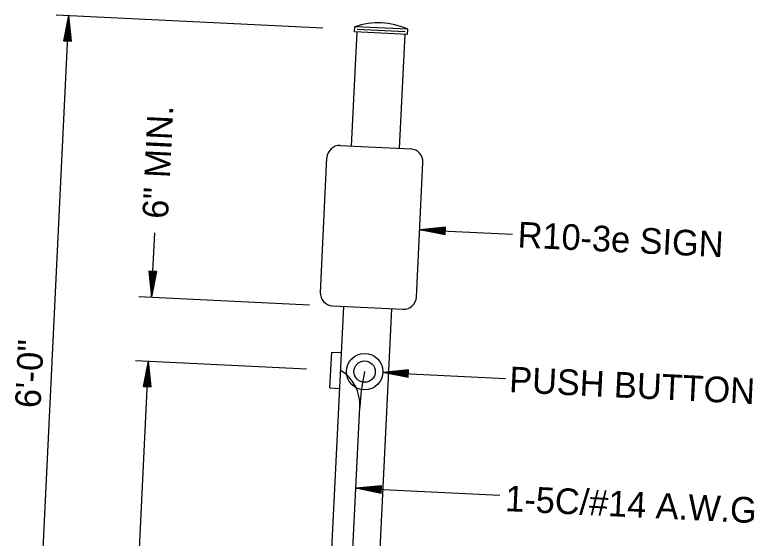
# Model space of a CAD drawing. Extents: x 661018 to 663325, y 642537 to 643074.
# Drawn here: x 661690.1 to 661787.2, y 642866.3 to 642935 of the extents above; entities that cross this region are included whole.
import ezdxf

# ---------------------------------------------------------------- set-up
doc = ezdxf.new("R2010")
doc.units = 0
doc.layers.add('R_Dimension', color=7, linetype='Continuous')

msp = doc.modelspace()

# ---------------------------------------------------------------- linework, layer by layer
at = {"layer": 'R_Dimension'}
for p, q in [((661692.169, 642831.3), (661697.202, 642934.948)), ((661695.52, 642935.03), (661730.561, 642933.328)), ((661696.534, 642931.607), (661697.202, 642934.948)), ((661697.544, 642931.558), (661697.202, 642934.948)), ((661696.618, 642931.603), (661697.175, 642934.386)), ((661697.46, 642931.562), (661697.175, 642934.386)), ((661696.704, 642931.599), (661697.147, 642933.807)), ((661696.788, 642931.595), (661697.12, 642933.247)), ((661697.29, 642931.571), (661697.12, 642933.247)), ((661697.374, 642931.567), (661697.147, 642933.807)), ((661734.709, 642932.79), (661734.741, 642933.463)), ((661741.724, 642933.123), (661734.741, 642933.463)), ((661741.372, 642932.803), (661735.062, 642933.11)), ((661741.692, 642932.45), (661741.724, 642933.123)), ((661696.876, 642931.591), (661697.092, 642932.677)), ((661696.96, 642931.587), (661697.065, 642932.115)), ((661697.118, 642931.579), (661697.065, 642932.115)), ((661697.204, 642931.575), (661697.092, 642932.677)), ((661734.318, 642917.8), (661735.045, 642932.773)), ((661741.692, 642932.45), (661734.709, 642932.79)), ((661740.628, 642917.494), (661741.355, 642932.467)), ((661696.534, 642931.607), (661697.544, 642931.558)), ((661732.846, 642917.872), (661742.1, 642917.423)), ((661730.224, 642898.603), (661731.082, 642916.271)), ((661742.843, 642897.991), (661743.701, 642915.658)), ((661746.662, 642907.166), (661743.272, 642906.824)), ((661743.272, 642906.824), (661755.458, 642906.233)), ((661746.613, 642906.156), (661743.272, 642906.824)), ((661746.658, 642907.082), (661743.834, 642906.797)), ((661746.617, 642906.24), (661743.834, 642906.797)), ((661746.654, 642906.996), (661744.413, 642906.769)), ((661746.621, 642906.326), (661744.413, 642906.769)), ((661746.65, 642906.912), (661744.974, 642906.742)), ((661746.646, 642906.826), (661745.544, 642906.714)), ((661746.613, 642906.156), (661746.662, 642907.166)), ((661708.057, 642897.993), (661708.466, 642906.406)), ((661746.626, 642906.41), (661744.974, 642906.742)), ((661746.63, 642906.498), (661745.544, 642906.714)), ((661746.642, 642906.74), (661746.106, 642906.687)), ((661746.634, 642906.582), (661746.106, 642906.687)), ((661707.716, 642901.383), (661708.057, 642897.993)), ((661708.726, 642901.334), (661707.716, 642901.383)), ((661707.8, 642901.379), (661708.085, 642898.555)), ((661707.886, 642901.375), (661708.113, 642899.134)), ((661707.97, 642901.371), (661708.14, 642899.694)), ((661708.056, 642901.366), (661708.168, 642900.265)), ((661708.726, 642901.334), (661708.057, 642897.993)), ((661708.641, 642901.338), (661708.085, 642898.555)), ((661708.556, 642901.342), (661708.113, 642899.134)), ((661708.471, 642901.346), (661708.14, 642899.694)), ((661708.142, 642901.362), (661708.195, 642900.827)), ((661708.384, 642901.35), (661708.168, 642900.265)), ((661708.3, 642901.355), (661708.195, 642900.827)), ((661706.375, 642898.075), (661728.796, 642896.986)), ((661730.159, 642832.151), (661733.297, 642896.767)), ((661731.825, 642896.839), (661741.079, 642896.39)), ((661736.469, 642831.845), (661739.607, 642896.461)), ((661731.484, 642886.061), (661731.713, 642890.773)), ((661731.713, 642890.773), (661733.003, 642890.71)), ((661704.789, 642830.688), (661707.649, 642889.58)), ((661705.966, 642889.662), (661728.387, 642888.573)), ((661706.981, 642886.239), (661707.649, 642889.58)), ((661707.99, 642886.19), (661707.649, 642889.58)), ((661707.065, 642886.235), (661707.621, 642889.018)), ((661707.151, 642886.231), (661707.593, 642888.439)), ((661707.82, 642886.198), (661707.593, 642888.439)), ((661707.906, 642886.194), (661707.621, 642889.018)), ((661741.817, 642888.427), (661738.427, 642888.085)), ((661741.813, 642888.343), (661738.989, 642888.058)), ((661741.768, 642887.417), (661741.817, 642888.427)), ((661707.235, 642886.227), (661707.566, 642887.879)), ((661707.736, 642886.202), (661707.566, 642887.879)), ((661738.427, 642888.085), (661754.538, 642887.303)), ((661741.768, 642887.417), (661738.427, 642888.085)), ((661741.772, 642887.501), (661738.989, 642888.058)), ((661741.809, 642888.257), (661739.568, 642888.03)), ((661741.776, 642887.587), (661739.568, 642888.03)), ((661741.804, 642888.173), (661740.128, 642888.003)), ((661741.78, 642887.671), (661740.128, 642888.003)), ((661741.8, 642888.087), (661740.699, 642887.975)), ((661741.784, 642887.759), (661740.699, 642887.975)), ((661741.796, 642888.001), (661741.261, 642887.948)), ((661741.788, 642887.843), (661741.261, 642887.948)), ((661707.322, 642886.223), (661707.538, 642887.308)), ((661707.406, 642886.218), (661707.511, 642886.746)), ((661707.564, 642886.211), (661707.511, 642886.746)), ((661707.65, 642886.207), (661707.538, 642887.308)), ((661706.981, 642886.239), (661707.99, 642886.19)), ((661731.484, 642886.061), (661732.774, 642885.999)), ((661731.802, 642809.544), (661735.395, 642883.544)), ((661738.272, 642873.228), (661734.882, 642872.887)), ((661734.882, 642872.887), (661753.794, 642871.969)), ((661738.223, 642872.219), (661734.882, 642872.887)), ((661738.268, 642873.144), (661735.444, 642872.86)), ((661738.227, 642872.303), (661735.444, 642872.86)), ((661738.263, 642873.058), (661736.023, 642872.832)), ((661738.231, 642872.389), (661736.023, 642872.832)), ((661738.259, 642872.974), (661736.583, 642872.804)), ((661738.235, 642872.473), (661736.583, 642872.804)), ((661738.255, 642872.888), (661737.153, 642872.777)), ((661738.239, 642872.56), (661737.153, 642872.777)), ((661738.251, 642872.803), (661737.715, 642872.749)), ((661738.223, 642872.219), (661738.272, 642873.228)), ((661738.243, 642872.644), (661737.715, 642872.749))]:
    msp.add_line(p, q, dxfattribs=at)
for radius in [2.387, 1.404]:
    msp.add_circle((661736.043, 642888.201), radius, dxfattribs=at)
for centre, radius, start, end in [((661737.81, 642924.574), 9.404, 65.39767, 109.04218), ((661732.764, 642916.189), 1.685, 87.21992, 177.21992), ((661742.019, 642915.74), 1.685, 357.21992, 87.21992), ((661731.906, 642898.522), 1.685, 177.21992, 267.21992), ((661741.161, 642898.072), 1.685, 267.21992, 357.21992), ((661730.242, 642883.916), 5.167, 355.86754, 59.18841), ((661768.735, 642881.28), 33.416, 168.04674, 176.1156)]:
    msp.add_arc(centre, radius, start, end, dxfattribs=at)

# ---------------------------------------------------------------- texts
for s, height, rotation, p in [('6" MIN.', 3.3692, 87.21992, (661710.207, 642908.202)), ('R10-3e SIGN', 3.36924, 357.21992, (661756.083, 642904.514)), ('6\'-0"', 3.3692, 87.21992, (661693.468, 642883.356)), ('PUSH BUTTON', 3.36924, 357.21992, (661754.974, 642885.501)), ('1-5C/#14 A.W.G', 3.36924, 357.21992, (661754.453, 642869.901))]:
    msp.add_text(s, height=height, rotation=rotation, dxfattribs=at).set_placement(p)

doc.saveas('drawing.dxf')
